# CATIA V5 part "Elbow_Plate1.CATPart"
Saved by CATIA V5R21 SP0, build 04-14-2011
Part number: Elbow_Plate1
Bounding box of the stored display mesh (mm): x 0 to 3, y -77.993 to -3.639, z -50.993 to 11
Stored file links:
  F:\教程\Robotic_Arm_Arduino_Kinect\机械臂CAD\Arm_Detailed_Design\Elbow_Plate1.CATPart
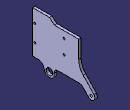
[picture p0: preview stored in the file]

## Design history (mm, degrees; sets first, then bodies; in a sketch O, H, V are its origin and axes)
Body1 (main body)
  DatumCurve1
  Sketch1 on yz-plane, origin (0, 0, 0), H (0, 1, 0), V (0, 0, 1)
    line L1 (-22.9934, 6) -> (-52.0346, 6)
    line L2 (-77.9934, -0.2265) -> (-77.9934, -39)
    line L3 (-48.1954, -39) -> (-22.1954, -39)
    line L4 (-22.9934, -14.8175) -> (-22.9934, 6)
    point P3 (-77.9934, -39)
    point P4 (-23.6185, -38.212)
    circle A1 centre (-57.9934, -45) radius 4
    point P5 (-57.9934, -45)
    arc A2 centre (-57.9934, -45) radius 6 from (-52.1146, -43.8) to (-63.9318, -45.8571) cw
    arc A3 centre (-48.1954, -43) radius 4 from (-52.1146, -43.8) to (-48.1954, -39) cw
    line L5 (-77.9934, -39) -> (-71.8498, -39)
    arc A4 centre (-71.8498, -47) radius 8 from (-63.9318, -45.8571) to (-71.8498, -39) ccw
    circle A5 centre (-7.9934, -45) radius 1.25
    point P12 (-7.9934, -45)
    arc A6 centre (-7.9934, -45) radius 4.3764 from (-4.8145, -41.9921) to (-11.1909, -47.9881) cw
    line L6 (-11.1909, -47.9881) -> (-17.8116, -40.9033)
    line L7 (-4.8145, -41.9921) -> (-17.5208, -28.5636)
    arc A7 centre (-22.1954, -45) radius 6 from (-17.8116, -40.9033) to (-22.1954, -39) ccw
    arc A8 centre (-2.9934, -14.8175) radius 20 from (-17.5208, -28.5636) to (-22.9934, -14.8175) cw
    line L8 (-77.9934, -0.2265) -> (-77.9934, 11)
    line L9 (-77.9934, 11) -> (-57.9934, 11)
    line L10 (-57.9934, 11) -> (-52.0346, 6)
    axis line L11 (-35.8571, 49.2803) -> (-35.8571, -128.5581)
    circle A9 centre (-75.4934, -4) radius 1.25
    point P26 (-75.4934, -4)
    circle A10 centre (-75.4934, -24) radius 1.25
    point P27 (-75.4934, -24)
    circle A11 centre (-40.4934, -2) radius 1.25
    point P28 (-40.4934, -2)
    circle A12 centre (-40.4934, -19) radius 1.25
    point P29 (-40.4934, -19)
    distance L2 L4 = 55
    radius A1 = 4
    radius A2 = 6
    radius A3 = 4
    radius A4 = 8
    distance P5 P12 = 50
    radius A5 = 1.25
    distance P5 H = 45
    distance P12 H = 45
    distance L1 L3 = 45
    radius A7 = 6
    radius A8 = 20
    distance L2 P5 = 20
    length L3 = 26
    distance L9 L5 = 50
    angle L10 L9 = 140
    length L9 = 20
    distance L4 V = 22.9934
    distance P27 L5 = 15
    radius A10 = 1.25
    distance P27 L2 = 2.5
    distance P26 L9 = 15
    distance P26 L8 = 2.5
    radius A9 = 1.25
    distance P28 L8 = 37.5
    radius A11 = 1.25
    distance P28 L1 = 8
    radius A12 = 1.25
    distance P29 L1 = 25
    distance P29 L2 = 37.5
    horizontal: L1 H, L3 H, L9 H
    vertical: L2 V, L4 V, L8 V, L11 V
    tangency: A2 L3, A3 A2, A3 L3, L5 A2, A4 A2, A4 L5, L6 A6, L7 A6, A7 L6, A7 L3, A8 L7, A8 L4
    coincidence: L3 P3
  Pad1: profile Sketch1, direction (1, 0, 0), length 3
  Sketch2 on start face of Pad1, origin (0, 0, 0), H (0, 1, 0), V (0, 0, 1)
    line L1 (-22.9934, 6) -> (-52.0346, 6)
    line L2 (-77.9934, -0.2265) -> (-77.9934, -39)
    line L3 (-48.1954, -39) -> (-22.1954, -39)
    line L4 (-22.9934, -14.8175) -> (-22.9934, 6)
    point P3 (-77.9934, -39)
    point P4 (-23.6185, -38.212)
    circle A1 centre (-57.9934, -45) radius 4
    point P5 (-57.9934, -45)
    arc A2 centre (-57.9934, -45) radius 6 from (-52.1146, -43.8) to (-63.9318, -45.8571) cw
    arc A3 centre (-48.1954, -43) radius 4 from (-52.1146, -43.8) to (-48.1954, -39) cw
    line L5 (-77.9934, -39) -> (-71.8498, -39)
    arc A4 centre (-71.8498, -47) radius 8 from (-63.9318, -45.8571) to (-71.8498, -39) ccw
    circle A5 centre (-7.9934, -45) radius 1.25
    point P12 (-7.9934, -45)
    arc A6 centre (-7.9934, -45) radius 4.3764 from (-4.8145, -41.9921) to (-11.1909, -47.9881) cw
    line L6 (-11.1909, -47.9881) -> (-17.8116, -40.9033)
    line L7 (-4.8145, -41.9921) -> (-17.5208, -28.5636)
    arc A7 centre (-22.1954, -45) radius 6 from (-17.8116, -40.9033) to (-22.1954, -39) ccw
    arc A8 centre (-2.9934, -14.8175) radius 20 from (-17.5208, -28.5636) to (-22.9934, -14.8175) cw
    line L8 (-77.9934, -0.2265) -> (-77.9934, 11)
    line L9 (-77.9934, 11) -> (-57.9934, 11)
    line L10 (-57.9934, 11) -> (-52.0346, 6)
    axis line L11 (-35.8571, 49.2803) -> (-35.8571, -128.5581)
    circle A9 centre (-75.4934, -4) radius 1.25
    point P26 (-75.4934, -4)
    circle A10 centre (-75.4934, -24) radius 1.25
    point P27 (-75.4934, -24)
    circle A11 centre (-40.4934, -2) radius 1.25
    point P28 (-40.4934, -2)
    circle A12 centre (-40.4934, -19) radius 1.25
    point P29 (-40.4934, -19)
    distance L2 L4 = 55
    radius A1 = 4
    radius A2 = 6
    radius A3 = 4
    radius A4 = 8
    distance P5 P12 = 50
    radius A5 = 1.25
    distance P5 H = 45
    distance P12 H = 45
    distance L1 L3 = 45
    radius A7 = 6
    radius A8 = 20
    distance L2 P5 = 20
    length L3 = 26
    distance L9 L5 = 50
    angle L10 L9 = 140
    length L9 = 20
    distance L4 V = 22.9934
    distance P27 L5 = 15
    radius A10 = 1.25
    distance P27 L2 = 2.5
    distance P26 L9 = 15
    distance P26 L8 = 2.5
    radius A9 = 1.25
    distance P28 L8 = 37.5
    radius A11 = 1.25
    distance P28 L1 = 8
    radius A12 = 1.25
    distance P29 L1 = 25
    distance P29 L2 = 37.5
    horizontal: L1 H, L3 H, L9 H
    vertical: L2 V, L4 V, L8 V, L11 V
    tangency: A2 L3, A3 A2, A3 L3, L5 A2, A4 A2, A4 L5, L6 A6, L7 A6, A7 L6, A7 L3, A8 L7, A8 L4
    coincidence: L3 P3
  Pad2: profile Sketch2, direction (1, 0, 0), length 3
